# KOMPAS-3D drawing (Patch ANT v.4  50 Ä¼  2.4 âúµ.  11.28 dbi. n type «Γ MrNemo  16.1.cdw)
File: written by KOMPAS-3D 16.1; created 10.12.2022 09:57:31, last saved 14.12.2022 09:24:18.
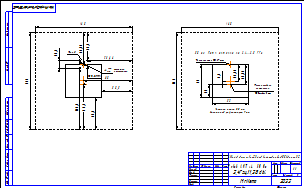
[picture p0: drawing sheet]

Sheet 1: custom format 500 x 310 mm, landscape

Title block, sheet 1: name: Patch ANT v.4  50 Ом / 2,4Ггц.11,28 dbi.; designation: https://www.lan23.ru/forum/node/851/page32; material: MrNemo; scale: 1:1; sheets: 1; organisation: 2022; stored path: G:\Patch ANT v.4  50 Ом от uve.cdw

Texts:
  высота над рефлектором 7мм
  50 ом Патч антенна на 2.4...2.5 ГГц
  Точка нулевого
  потенциала
  Ø Стойки 5mm
  Толщина патча 0,5 мм
  Точка запитки Ø 1,27 mm
  Type N
  Отверстие
  в рефлекторе
  Ø 2,5 mm
Dimensions and other numbers on the sheet: 52,5; 50,5; 80; 53,25; 12,7; 73,66; 46,9; 100,4; 160; 22; 59; 26,75; 55; 5,5; 32,25; 4; 74,5; 1:1; 1; 2,4Ггц.11,28 dbi.; 2022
